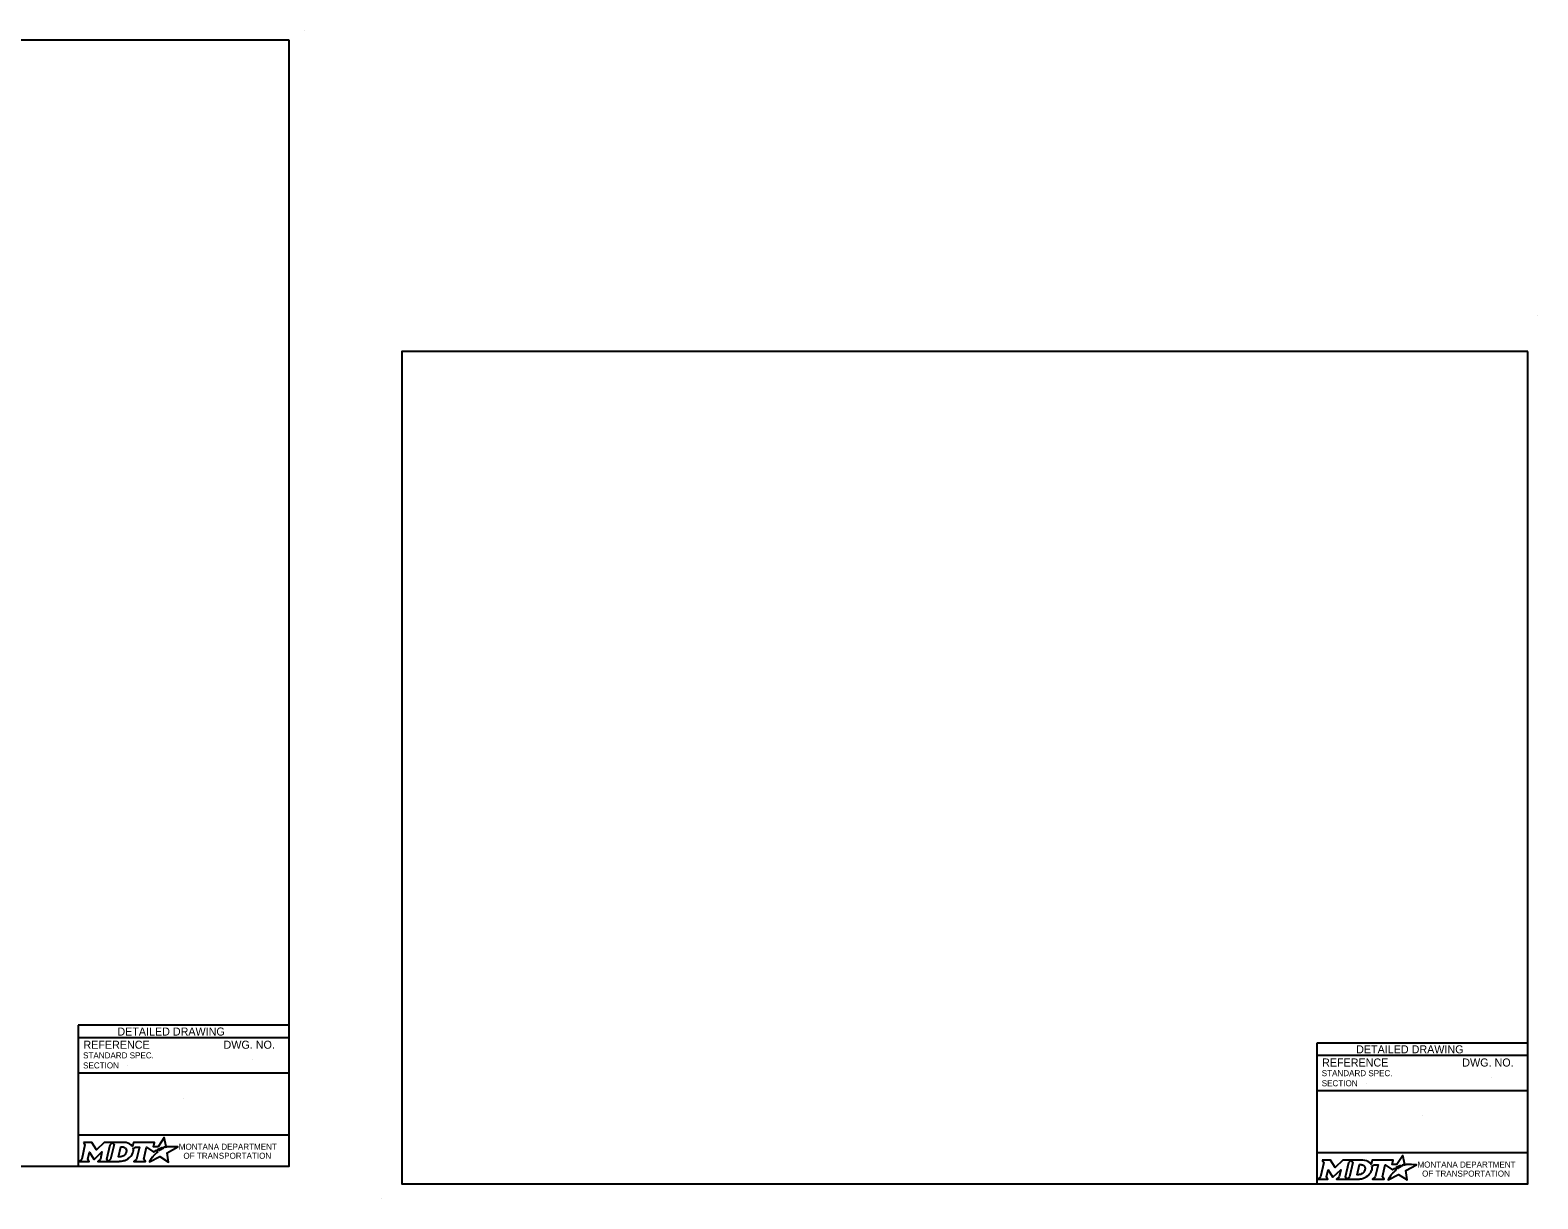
# Model space of a CAD drawing. Extents: x 49991.4 to 50021, y 49987.6 to 50011.4.
# Drawn here: x 50006.04 to 50021.04, y 49999.74 to 50011.36 of the extents above; entities that cross this region are included whole.
import ezdxf

# ---------------------------------------------------------------- set-up
doc = ezdxf.new("R2010")
doc.units = 0
for name, color, linetype in [('Default', 7, 'Continuous'), ('Level 1', 7, 'Continuous'), ('Level 2', 7, 'Continuous'), ('Level 4', 7, 'Continuous')]:
    doc.layers.add(name, color=color, linetype=linetype)

msp = doc.modelspace()

# ---------------------------------------------------------------- linework, layer by layer
at = {"layer": 'Default'}
for points in [[(50019.7, 50000.068), (50019.69, 50000.074), (50019.702, 50000.076), (50019.713, 50000.078), (50019.696, 50000.168), (50019.636, 50000.077), (50019.589, 50000.076), (50019.599, 50000.12), (50019.39, 50000.121), (50019.38, 50000.078), (50019.374, 50000.086)], [(50018.893, 50000.121), (50018.907, 50000.097), (50018.874, 49999.954), (50018.848, 49999.931), (50018.95, 49999.931), (50018.936, 49999.954), (50018.952, 50000.024), (50018.996, 49999.955), (50019.002, 49999.955), (50019.077, 50000.025), (50019.06, 49999.954), (50019.035, 49999.932), (50019.137, 49999.932), (50019.123, 49999.955), (50019.156, 50000.097)], [(50019.156, 50000.097), (50019.182, 50000.121), (50019.099, 50000.121), (50019.02, 50000.048), (50018.975, 50000.12), (50018.893, 50000.121)], [(50019.295, 50000.121), (50019.182, 50000.121), (50019.196, 50000.098), (50019.163, 49999.954), (50019.137, 49999.932), (50019.248, 49999.932)], [(50019.319, 50000.034), (50019.318, 50000.026), (50019.315, 50000.017), (50019.311, 50000.008), (50019.305, 50000.001), (50019.299, 49999.994), (50019.291, 49999.988), (50019.282, 49999.983), (50019.273, 49999.979), (50019.264, 49999.977), (50019.255, 49999.976), (50019.239, 49999.976), (50019.263, 50000.076), (50019.279, 50000.076), (50019.286, 50000.075), (50019.294, 50000.073), (50019.301, 50000.07), (50019.307, 50000.066), (50019.311, 50000.061), (50019.315, 50000.055), (50019.318, 50000.049), (50019.319, 50000.042), (50019.32, 50000.038), (50019.319, 50000.034)], [(50019.387, 50000.062), (50019.411, 50000.075), (50019.448, 50000.075), (50019.42, 49999.954), (50019.392, 49999.931), (50019.508, 49999.931), (50019.491, 49999.954), (50019.52, 50000.075), (50019.591, 50000.023), (50019.612, 50000.038), (50019.632, 50000.027)], [(50019.576, 49999.971), (50019.561, 49999.947), (50019.556, 49999.939), (50019.55, 49999.931), (50019.548, 49999.926), (50019.653, 49999.979), (50019.737, 49999.924), (50019.724, 50000.017), (50019.831, 50000.075), (50019.782, 50000.076), (50019.751, 50000.077), (50019.731, 50000.077), (50019.724, 50000.075), (50019.719, 50000.074), (50019.711, 50000.072), (50019.7, 50000.068)], [(50019.59, 49999.987), (50019.59, 49999.987)], [(50019.65, 50000.04), (50019.648, 50000.039), (50019.629, 50000.048), (50019.639, 50000.054), (50019.644, 50000.056), (50019.652, 50000.06), (50019.658, 50000.063), (50019.666, 50000.066), (50019.673, 50000.068), (50019.685, 50000.061), (50019.681, 50000.059), (50019.676, 50000.056), (50019.672, 50000.054), (50019.667, 50000.051), (50019.665, 50000.05), (50019.662, 50000.049), (50019.66, 50000.047), (50019.658, 50000.046), (50019.655, 50000.044), (50019.652, 50000.042), (50019.65, 50000.04)], [(50019.293, 49999.939), (50019.302, 49999.942), (50019.315, 49999.947), (50019.335, 49999.958)]]:
    msp.add_lwpolyline(points, dxfattribs=at)
for centre, radius, start, end in [((50019.274, 50000.059), 0.118, 300.9103, 339.1383), ((50019.319, 50000.042), 0.0709, 339.5329, 15.8582)]:
    msp.add_arc(centre, radius, start, end, dxfattribs=at)
for centre, major_axis, ratio, start_param, end_param in [((50019.293, 50000.073), (0.0834, -0.0037), 0.568097, 0.61298, 1.570796), ((50019.349, 50000.081), (0.0361, -0.0295), 0.469099, 1.225588, 1.570796), ((50019.583, 49999.979), (-0.00694, -0.00806), 0.008222, 0, 3.137361), ((50019.6, 49999.997), (-0.0098, -0.0102), 0.016458, 3.141593, 6.279097), ((50019.621, 50000.017), (-0.0112, -0.0097), 0.021651, 3.157348, 6.283185), ((50019.248, 50000.08), (0, 0.148), 0.987302, 3.139398, 3.456847)]:
    msp.add_ellipse(centre, major_axis=major_axis, ratio=ratio, start_param=start_param, end_param=end_param, dxfattribs=at)
at = {"layer": 'Level 1'}
for p, q in [((50008.765, 50011.363), (50008.765, 50011.363)), ((50021.038, 50008.524), (50021.038, 50008.524)), ((50009.537, 49999.736), (50009.537, 49999.736))]:
    msp.add_line(p, q, dxfattribs=at)
for points in [[(50008.615, 50011.263), (50000.336, 50011.263), (50000.336, 50000.062), (50008.615, 50000.062)], [(50020.938, 50008.165), (50009.737, 50008.165), (50009.737, 49999.886), (50020.938, 49999.886)]]:
    msp.add_lwpolyline(points, close=True, dxfattribs=at)
at = {"layer": 'Level 2'}
for p, q in [((50008.615, 50001.462), (50006.515, 50001.462)), ((50006.515, 50001.462), (50006.515, 50000.062)), ((50008.615, 50001.337), (50006.515, 50001.337)), ((50007.009, 50001.063), (50007.009, 50001.063)), ((50008.251, 50001.122), (50008.251, 50001.122)), ((50008.615, 50000.987), (50006.515, 50000.987)), ((50007.565, 50000.738), (50007.565, 50000.738)), ((50008.615, 50000.369), (50006.515, 50000.369))]:
    msp.add_line(p, q, dxfattribs=at)
for points in [[(50006.57, 50000.297), (50006.584, 50000.274), (50006.551, 50000.131), (50006.525, 50000.108), (50006.627, 50000.108), (50006.613, 50000.131), (50006.629, 50000.201), (50006.673, 50000.132), (50006.678, 50000.132), (50006.753, 50000.202), (50006.737, 50000.13), (50006.712, 50000.108), (50006.814, 50000.108), (50006.8, 50000.132), (50006.833, 50000.274)], [(50006.833, 50000.274), (50006.859, 50000.297), (50006.776, 50000.297), (50006.697, 50000.224), (50006.652, 50000.297), (50006.57, 50000.297)], [(50006.972, 50000.297), (50006.859, 50000.297), (50006.873, 50000.275), (50006.839, 50000.131), (50006.814, 50000.108), (50006.925, 50000.108)], [(50007.377, 50000.245), (50007.367, 50000.25), (50007.378, 50000.253), (50007.39, 50000.255), (50007.373, 50000.345), (50007.313, 50000.254), (50007.266, 50000.253), (50007.276, 50000.297), (50007.067, 50000.297), (50007.057, 50000.255), (50007.051, 50000.263)], [(50006.996, 50000.211), (50006.995, 50000.203), (50006.992, 50000.193), (50006.988, 50000.185), (50006.982, 50000.178), (50006.976, 50000.171), (50006.968, 50000.164), (50006.959, 50000.16), (50006.95, 50000.156), (50006.941, 50000.154), (50006.932, 50000.153), (50006.916, 50000.153), (50006.94, 50000.253), (50006.956, 50000.253), (50006.963, 50000.252), (50006.971, 50000.25), (50006.977, 50000.247), (50006.983, 50000.243), (50006.988, 50000.238), (50006.992, 50000.232), (50006.995, 50000.226), (50006.996, 50000.218), (50006.996, 50000.215), (50006.996, 50000.211)], [(50006.97, 50000.116), (50006.979, 50000.118), (50006.992, 50000.124), (50007.012, 50000.135)], [(50007.064, 50000.238), (50007.088, 50000.251), (50007.125, 50000.251), (50007.097, 50000.131), (50007.069, 50000.108), (50007.185, 50000.108), (50007.168, 50000.131), (50007.196, 50000.251), (50007.268, 50000.2), (50007.289, 50000.215), (50007.309, 50000.204)], [(50007.253, 50000.148), (50007.237, 50000.124), (50007.233, 50000.116), (50007.227, 50000.107), (50007.225, 50000.103), (50007.33, 50000.156), (50007.414, 50000.101), (50007.401, 50000.194), (50007.508, 50000.252), (50007.458, 50000.253), (50007.428, 50000.253), (50007.407, 50000.254), (50007.401, 50000.252), (50007.396, 50000.251), (50007.387, 50000.249), (50007.377, 50000.245)], [(50007.267, 50000.164), (50007.267, 50000.164)], [(50007.327, 50000.217), (50007.324, 50000.215), (50007.306, 50000.225), (50007.316, 50000.231), (50007.32, 50000.233), (50007.329, 50000.237), (50007.335, 50000.239), (50007.343, 50000.243), (50007.35, 50000.245), (50007.362, 50000.238), (50007.358, 50000.236), (50007.353, 50000.233), (50007.349, 50000.231), (50007.344, 50000.228), (50007.342, 50000.227), (50007.339, 50000.225), (50007.337, 50000.224), (50007.334, 50000.222), (50007.332, 50000.221), (50007.329, 50000.219), (50007.327, 50000.217)]]:
    msp.add_lwpolyline(points, dxfattribs=at)
for centre, radius, start, end in [((50006.951, 50000.236), 0.118, 300.9103, 339.1383), ((50006.995, 50000.219), 0.0709, 339.5329, 15.8582)]:
    msp.add_arc(centre, radius, start, end, dxfattribs=at)
for centre, major_axis, ratio, start_param, end_param in [((50006.97, 50000.25), (0.0834, -0.0037), 0.568097, 0.61298, 1.570796), ((50007.026, 50000.257), (0.0361, -0.0295), 0.469099, 1.225588, 1.570796), ((50007.26, 50000.156), (-0.00694, -0.00806), 0.008222, 0, 3.137361), ((50007.276, 50000.174), (-0.0098, -0.0102), 0.016458, 3.141593, 6.279097), ((50007.297, 50000.194), (-0.0112, -0.0097), 0.021651, 3.157348, 6.283185), ((50006.925, 50000.257), (0, 0.148), 0.987302, 3.139398, 3.456847)]:
    msp.add_ellipse(centre, major_axis=major_axis, ratio=ratio, start_param=start_param, end_param=end_param, dxfattribs=at)
at = {"layer": 'Level 4'}
for p, q in [((50020.938, 50001.286), (50018.838, 50001.286)), ((50018.838, 50001.286), (50018.838, 49999.886)), ((50020.938, 50001.161), (50018.838, 50001.161)), ((50019.332, 50000.886), (50019.332, 50000.886)), ((50020.574, 50000.946), (50020.574, 50000.946)), ((50020.938, 50000.811), (50018.838, 50000.811)), ((50019.888, 50000.562), (50019.888, 50000.562)), ((50020.938, 50000.193), (50018.838, 50000.193))]:
    msp.add_line(p, q, dxfattribs=at)

# ---------------------------------------------------------------- texts
at = {"layer": 'Default'}
for s, p in [('MONTANA DEPARTMENT', (50019.84, 50000.047)), ('OF TRANSPORTATION', (50019.886, 49999.957))]:
    msp.add_text(s, height=0.06, rotation=360, dxfattribs=at).set_placement(p)
at = {"layer": 'Level 2'}
for s, height, p in [('DETAILED DRAWING', 0.0799, (50006.906, 50001.36)), ('STANDARD SPEC.', 0.06, (50006.565, 50001.133)), ('REFERENCE', 0.08, (50006.568, 50001.229)), ('DWG. NO.', 0.08, (50007.962, 50001.229)), ('SECTION', 0.06, (50006.565, 50001.033))]:
    msp.add_text(s, height=height, dxfattribs=at).set_placement(p)
for s, p in [('MONTANA DEPARTMENT', (50007.517, 50000.224)), ('OF TRANSPORTATION', (50007.563, 50000.134))]:
    msp.add_text(s, height=0.06, rotation=360, dxfattribs=at).set_placement(p)
at = {"layer": 'Level 4'}
for s, height, p in [('DETAILED DRAWING', 0.0799, (50019.23, 50001.183)), ('REFERENCE', 0.08, (50018.891, 50001.052)), ('DWG. NO.', 0.08, (50020.286, 50001.052)), ('STANDARD SPEC.', 0.06, (50018.888, 50000.956)), ('SECTION', 0.06, (50018.888, 50000.856))]:
    msp.add_text(s, height=height, dxfattribs=at).set_placement(p)

doc.saveas('drawing.dxf')
